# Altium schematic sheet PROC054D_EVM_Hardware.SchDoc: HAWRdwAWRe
size 558 x 431 mm; Date: Not shown in title block; ApprovedBy: Not shown in title block; CheckedBy: Not shown in title block; Author: Not shown in title block; CompanyName: Not shown in title block; DrawnBy: a0271760; Engineer: Not shown in title block; Organization: Not shown in title block; Address1: Not shown in title block; Address2: Not shown in title block; Address3: Not shown in title block; Address4: Not shown in title block; DocumentNumber: 18; Revision: Use project pAWRameter SCH_Rev; SheetNumber: 18; SheetTotal: 19; PageSetup: Record=PageOptions¦CenterHorizontal=True¦CenterVertical=True¦PrintScale=1.00¦XCorrection=1.00¦YCorrection=1.00¦PrintKind=0¦BorderSize=5000000¦LeftOffset=0¦BottomOffset=0¦Orientation=2¦PaperLength=1000¦PaperWidth=1000¦Scale=100¦PaperSource=15¦PrintQuality=600¦MediaType=1¦DitherType=10¦PaperKind=Letter¦PrintScaleMode=1
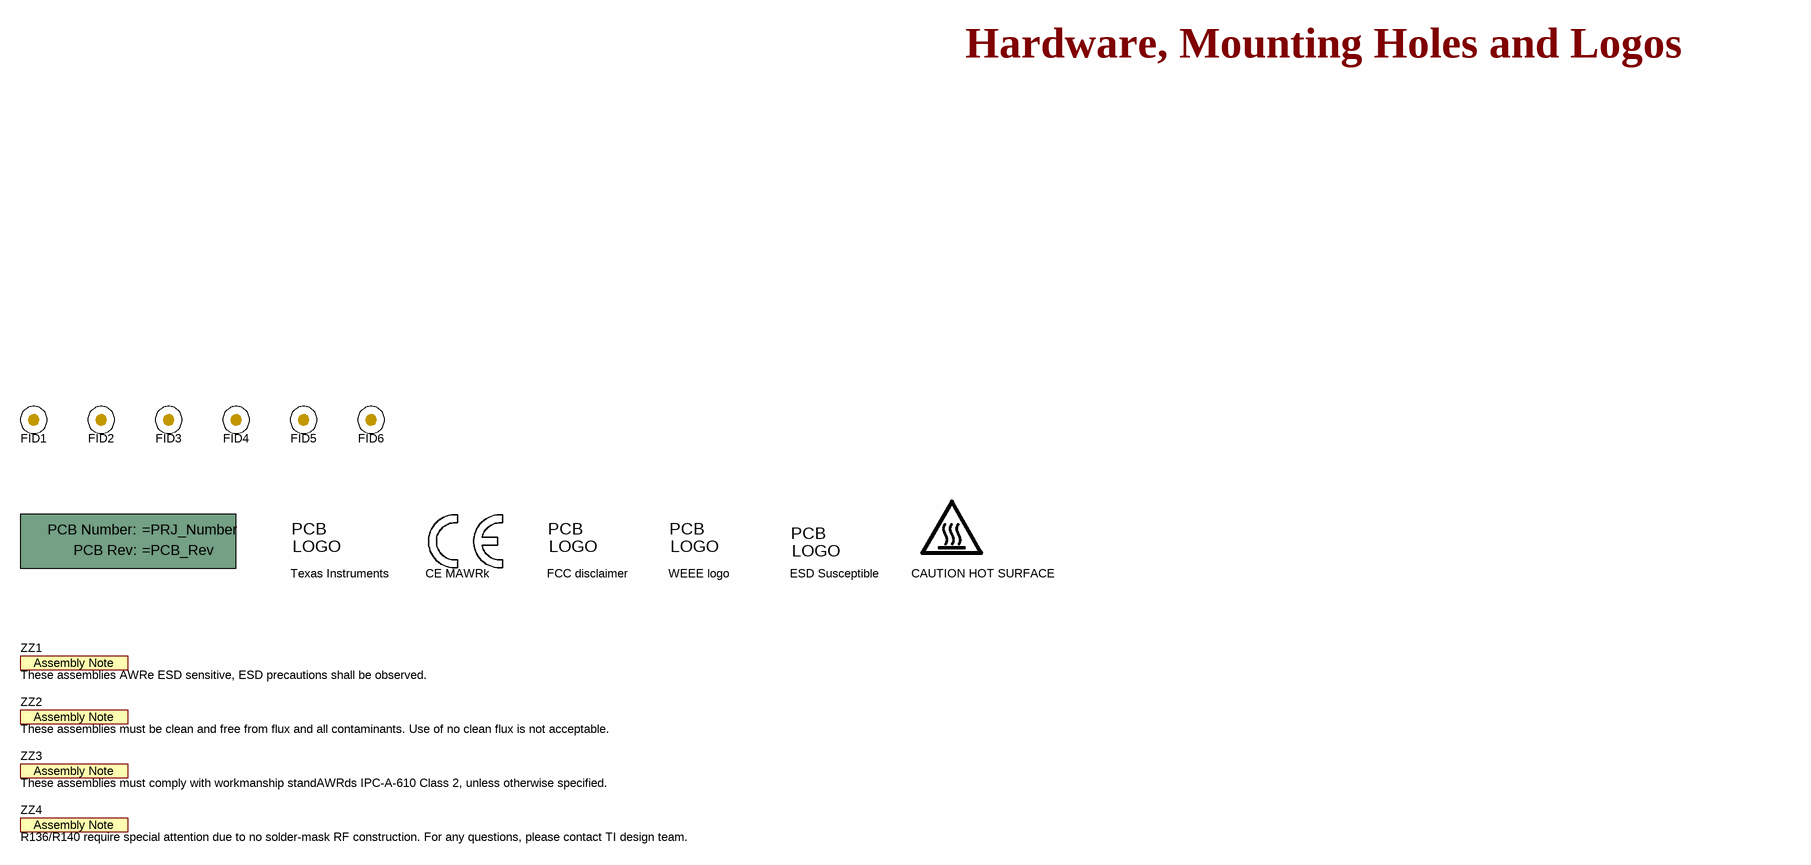
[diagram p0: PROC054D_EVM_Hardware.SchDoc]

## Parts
!PCB1  Printed Circuit Board  (value not drawn)  (mechanical)
FID1  Fiducial  [Fiducial10-20]  (value not drawn)
FID2  Fiducial  [Fiducial10-20]  (value not drawn)
FID3  Fiducial  [Fiducial10-20]  (value not drawn)
FID4  Fiducial  [Fiducial10-20]  (value not drawn)
FID5  Fiducial  [Fiducial10-20]  (value not drawn)
FID6  Fiducial  [Fiducial10-20]  (value not drawn)
Logo1  CE MAWRk  [CE_Mark_5mm]  (no BOM)
Logo2  Texas Instruments  [TI_Stacked_Overlay_Small]  (no BOM)
Logo3  FCC disclaimer  [FCC_disclaimer]  (no BOM)
Logo4  WEEE logo  [WEEE_Minimum]  (no BOM)
Logo5  ESD Susceptible  [ESD_Overlay_Large]  (no BOM)
LOGO6  CAUTION HOT SURFACE  [IEC_HotSurface_Large]  (no BOM)
ZZ1  These assemblies AWRe ESD sensitive, ESD precautions shall be observed.  [AssemblyNote]  (no BOM)
ZZ2  These assemblies must be clean and free from flux and all contaminants. Use of no clean flux is not acceptable.  [AssemblyNote]  (no BOM)
ZZ3  These assemblies must comply with workmanship standAWRds IPC-A-610 Class 2, unless otherwise specified.  [AssemblyNote]  (no BOM)
ZZ4  R136/R140 require special attention due to no solder-mask RF construction. For any questions, please contact TI design team.  [AssemblyNote]  (no BOM)

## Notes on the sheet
- Hardware, Mounting Holes and Logos

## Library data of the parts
!PCB1 = CMP-0003618-2: Manufacturer: Any
FID1-FID6 = CMP-0077181-1: Fiducial mark.  There is nothing to buy or mount.
Logo1 = CMP-0074844-1: CE Mark; SymbolCreator: a0412235
Logo2 = CMP-0074838-1: Texas Instrument Corporate Signature; SymbolCreator: a0412235; Lib Reference: TI_Logo; Library Reference: Logo
Logo3 = CMP-0074847-1: FCC_disclaimer; Library Reference: Logo
Logo4 = CMP-0074769-1
Logo5 = CMP-0074840-1: ESD Susceptible Symbol; SymbolCreator: a0412235; Lib Reference: ESD_Susceptible
LOGO6 = CMP-0074837-1: IEC 61010-1 Hot Surface Warning; SymbolCreator: a0412235
ZZ1 = CMP-0077236-1: These assemblies are ESD sensitive, ESD precautions shall be observed.
ZZ2 = CMP-0077237-1
ZZ3 = CMP-0077238-1: These assemblies must comply with workmanship standards IPC-A-610 Class 2, unless otherwise specified.
ZZ4 = CMP-0077238-1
